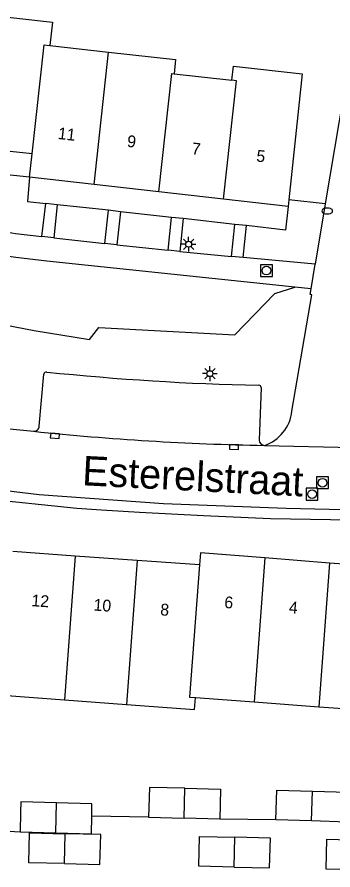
# Model space of a CAD drawing. Extents: x 132994 to 136000, y 393499 to 395512.
# Drawn here: x 133760.3 to 133787.1, y 394879.5 to 394951.9 of the extents above; entities that cross this region are included whole.
import ezdxf

# ---------------------------------------------------------------- set-up
doc = ezdxf.new("R2010")
doc.units = 0
for name, color, linetype in [('gg-afsc-erfafscheiding', 7, 'Continuous'), ('gg-afsc-hekwerk', 7, 'Continuous'), ('gg-anno-huisnummerreeks BGT', 7, 'Continuous'), ('gg-anno-openbare ruimte label', 7, 'Continuous'), ('gg-bbg-bijgebouw', 7, 'Continuous'), ('gg-bbg-hoofdgebouw', 7, 'Continuous'), ('gg-bbg-tussenscheiding', 7, 'Continuous'), ('gg-knt-verharding', 7, 'Continuous'), ('gg-knt-verharding nz', 7, 'Continuous'), ('gt-grn-groengrens', 7, 'Continuous'), ('gt-grn-vlakafsluiter', 7, 'Continuous'), ('gt-grn-weggrens', 7, 'Continuous'), ('gt-symb-brandkraan', 7, 'Continuous'), ('gt-symb-kolk', 7, 'Continuous'), ('gt-symb-lichtmast', 7, 'Continuous'), ('gt-symb-rioolschacht', 7, 'Continuous')]:
    doc.layers.add(name, color=color, linetype=linetype)

# ---------------------------------------------------------------- blocks, each defined once
blk = doc.blocks.new('gt0-BR')
at = {"layer": 'gt-symb-brandkraan'}
for centre, radius, start, end in [((-0.244, 0), 0.206, 107.56694, 252.43307), ((0.599, -2.664), 3, 106.89205, 107.56694), ((0, -0.691), 0.938, 73.10799, 106.89205), ((-0.599, -2.664), 3, 72.43309, 73.10799), ((0.244, 0), 0.206, 287.56695, 72.43309), ((0.599, 2.664), 3, 252.43307, 253.10797), ((0, 0.691), 0.938, 253.10797, 286.89206), ((-0.599, 2.664), 3, 286.89206, 287.56695)]:
    blk.add_arc(centre, radius, start, end, dxfattribs=at)
blk = doc.blocks.new('gt0-RS')
at = {"layer": 'gt-symb-rioolschacht'}
blk.add_lwpolyline([(-0.5, -0.5), (0.5, -0.5), (0.5, 0.5), (-0.5, 0.5)], close=True, dxfattribs=at)
blk.add_circle((0, 0), 0.375, dxfattribs=at)
blk = doc.blocks.new('gt0-LMAST')
at = {"layer": 'gt-symb-lichtmast'}
for p, q in [((-0.182, 0.173), (-0.447, 0.438)), ((-0.005, 0.246), (-0.005, 0.621)), ((0.172, 0.173), (0.437, 0.438)), ((-0.255, -0.004), (-0.63, -0.004)), ((-0.182, -0.181), (-0.447, -0.446)), ((-0.005, -0.254), (-0.005, -0.629)), ((0.437, -0.446), (0.172, -0.181)), ((0.245, -0.004), (0.62, -0.004))]:
    blk.add_line(p, q, dxfattribs=at)
blk.add_circle((-0.005, -0.004), 0.25, dxfattribs=at)
blk = doc.blocks.new('gt0-KOLK')
at = {"layer": 'gt-symb-kolk'}
blk.add_lwpolyline([(0, 0), (0.375, 0), (0.375, 0.4), (-0.375, 0.4), (-0.375, 0), (0, 0)], dxfattribs=at)

msp = doc.modelspace()

# ---------------------------------------------------------------- linework, layer by layer
at = {"layer": 'gg-afsc-erfafscheiding'}
for p, q in [((133771.458, 394883.991), (133766.623, 394884.084)), ((133782.257, 394883.762), (133777.502, 394883.836)), ((133757.915, 394882.911), (133760.541, 394882.748))]:
    msp.add_line(p, q, dxfattribs=at)
at = {"layer": 'gg-afsc-hekwerk'}
for p, q in [((133789.305, 394953.107), (133786.435, 394936.039)), ((133786.435, 394936.039), (133783.351, 394936.365))]:
    msp.add_line(p, q, dxfattribs=at)
at = {"layer": 'gg-bbg-bijgebouw'}
for p, q in [((133760.585, 394884.425), (133760.541, 394882.748)), ((133766.594, 394882.589), (133766.623, 394884.084)), ((133771.458, 394883.991), (133774.48, 394883.914)), ((133777.502, 394883.836), (133774.48, 394883.914)), ((133785.287, 394883.675), (133782.257, 394883.762)), ((133788.317, 394883.587), (133785.287, 394883.675)), ((133760.541, 394882.748), (133763.568, 394882.668)), ((133763.568, 394882.668), (133766.594, 394882.589))]:
    msp.add_line(p, q, dxfattribs=at)
for points in [[(133774.542, 394886.451), (133771.518, 394886.527), (133771.458, 394883.991)], [(133774.542, 394886.451), (133777.566, 394886.375), (133777.502, 394883.836)], [(133782.257, 394883.762), (133782.331, 394886.301), (133785.357, 394886.212)], [(133785.357, 394886.212), (133788.382, 394886.124), (133788.317, 394883.587)], [(133763.625, 394885.209), (133760.607, 394885.287), (133760.585, 394884.425)], [(133766.623, 394884.084), (133766.643, 394885.13), (133763.625, 394885.209)], [(133764.31, 394880.057), (133761.296, 394880.132), (133761.36, 394882.672), (133764.375, 394882.596)], [(133764.31, 394880.057), (133767.325, 394879.981), (133767.389, 394882.52), (133764.375, 394882.596)], [(133778.718, 394879.76), (133775.709, 394879.831), (133775.77, 394882.37), (133778.778, 394882.299)], [(133778.718, 394879.76), (133781.727, 394879.688), (133781.787, 394882.228), (133778.778, 394882.299)], [(133789.539, 394879.522), (133786.529, 394879.584), (133786.582, 394882.124), (133789.592, 394882.061)]]:
    msp.add_lwpolyline(points, dxfattribs=at)
at = {"layer": 'gg-bbg-hoofdgebouw'}
for p, q in [((133763.075, 394949.456), (133768.061, 394948.9)), ((133773.612, 394947.062), (133778.518, 394946.516)), ((133761.574, 394940.266), (133756.303, 394940.845)), ((133761.354, 394938.285), (133761.574, 394940.266)), ((133766.838, 394937.663), (133761.354, 394938.285)), ((133772.323, 394937.041), (133766.838, 394937.663)), ((133777.807, 394936.419), (133772.323, 394937.041)), ((133783.291, 394935.797), (133777.807, 394936.419)), ((133783.351, 394936.365), (133783.291, 394935.797)), ((133765.217, 394906.152), (133759.945, 394906.525)), ((133770.488, 394905.779), (133765.217, 394906.152)), ((133786.81, 394905.557), (133781.331, 394905.988)), ((133775.76, 394905.406), (133770.488, 394905.779)), ((133792.29, 394905.127), (133786.81, 394905.557)), ((133759.041, 394894.34), (133764.312, 394893.954)), ((133764.312, 394893.954), (133769.582, 394893.568)), ((133775.43, 394894.145), (133780.425, 394893.775)), ((133780.425, 394893.775), (133785.906, 394893.369)), ((133785.906, 394893.369), (133791.591, 394892.948))]:
    msp.add_line(p, q, dxfattribs=at)
for points in [[(133757.199, 394949.706), (133757.466, 394952.097), (133763.298, 394951.444), (133763.075, 394949.456)], [(133768.061, 394948.9), (133773.744, 394948.267), (133773.612, 394947.062)], [(133778.518, 394946.516), (133778.653, 394947.719), (133784.481, 394947.064), (133783.351, 394936.365)], [(133781.331, 394905.988), (133775.851, 394906.418), (133775.76, 394905.406)], [(133769.582, 394893.568), (133775.354, 394893.146), (133775.43, 394894.145)]]:
    msp.add_lwpolyline(points, dxfattribs=at)
at = {"layer": 'gg-bbg-tussenscheiding'}
for p, q in [((133766.838, 394937.663), (133768.061, 394948.9)), ((133765.217, 394906.152), (133764.312, 394893.954)), ((133781.331, 394905.988), (133780.425, 394893.775)), ((133770.488, 394905.779), (133769.582, 394893.568)), ((133786.81, 394905.557), (133785.906, 394893.369)), ((133774.48, 394883.914), (133774.542, 394886.451)), ((133785.287, 394883.675), (133785.357, 394886.212)), ((133763.568, 394882.668), (133763.625, 394885.209)), ((133764.31, 394880.057), (133764.375, 394882.596)), ((133778.718, 394879.76), (133778.778, 394882.299))]:
    msp.add_line(p, q, dxfattribs=at)
for points in [[(133761.574, 394940.266), (133762.58, 394949.511), (133763.075, 394949.456)], [(133772.323, 394937.041), (133773.416, 394947.084), (133773.612, 394947.062)], [(133777.807, 394936.419), (133778.901, 394946.473), (133778.518, 394946.516)], [(133775.76, 394905.406), (133774.927, 394894.182), (133775.43, 394894.145)]]:
    msp.add_lwpolyline(points, dxfattribs=at)
at = {"layer": 'gg-knt-verharding'}
for p, q in [((133761.354, 394938.285), (133758.478, 394938.601)), ((133762.386, 394933.255), (133762.72, 394936.06)), ((133763.684, 394935.952), (133762.72, 394936.06)), ((133763.684, 394935.952), (133763.412, 394933.141)), ((133768.059, 394935.483), (133763.684, 394935.952)), ((133786.435, 394936.039), (133785.588, 394930.905)), ((133767.737, 394932.671), (133768.059, 394935.483)), ((133769.074, 394935.368), (133768.059, 394935.483)), ((133769.074, 394935.368), (133768.754, 394932.558)), ((133773.4, 394934.872), (133769.074, 394935.368)), ((133773.103, 394932.101), (133773.4, 394934.872)), ((133774.386, 394934.775), (133773.4, 394934.872)), ((133774.386, 394934.775), (133774.101, 394931.987)), ((133778.77, 394934.278), (133774.386, 394934.775)), ((133778.484, 394931.564), (133778.77, 394934.278)), ((133779.771, 394934.183), (133778.77, 394934.278)), ((133779.468, 394931.478), (133779.771, 394934.183)), ((133763.412, 394933.141), (133762.386, 394933.255)), ((133763.412, 394933.141), (133767.737, 394932.671)), ((133768.754, 394932.558), (133767.737, 394932.671)), ((133768.754, 394932.558), (133773.103, 394932.101)), ((133774.101, 394931.987), (133773.103, 394932.101)), ((133774.101, 394931.987), (133778.484, 394931.564)), ((133779.468, 394931.478), (133778.484, 394931.564)), ((133785.588, 394930.905), (133779.468, 394931.478)), ((133785.244, 394928.81), (133783.857, 394928.956)), ((133762.165, 394917.161), (133762.564, 394921.589)), ((133781.01, 394920.452), (133780.839, 394915.995)), ((133759.68, 394916.958), (133761.698, 394916.736))]:
    msp.add_line(p, q, dxfattribs=at)
for points in [[(133761.354, 394938.285), (133761.172, 394936.226), (133762.72, 394936.06)], [(133783.291, 394935.797), (133783.066, 394933.809), (133779.771, 394934.183)], [(133783.857, 394928.956), (133762.808, 394931.174), (133760.198, 394931.468), (133758.542, 394931.717), (133757.019, 394932.05), (133754.664, 394932.662), (133751.569, 394933.436), (133750.125, 394933.754), (133748.508, 394934.067), (133747.291, 394934.262), (133745.966, 394934.42), (133744.197, 394934.56), (133742.868, 394934.609), (133741.429, 394934.614), (133740.938, 394934.587), (133740.577, 394934.514), (133740.21, 394934.368), (133739.836, 394934.124), (133739.598, 394933.881), (133739.383, 394933.586), (133739.167, 394933.097), (133739.023, 394932.554), (133738.938, 394932.002)], [(133757.962, 394933.908), (133760.149, 394933.506), (133762.386, 394933.255)], [(133783.621, 394918.441), (133785.302, 394928.306), (133785.177, 394928.33), (133785.244, 394928.81)], [(133792.763, 394909.128), (133786.892, 394909.236), (133781.809, 394909.31), (133776.125, 394909.577), (133770.682, 394909.854), (133767.444, 394910.035), (133765.369, 394910.183), (133757.147, 394911.025), (133755.09, 394911.267), (133751.549, 394911.747), (133749.282, 394912.083), (133744.071, 394912.918), (133740.605, 394913.512), (133738.386, 394913.916), (133735.537, 394914.513)]]:
    msp.add_lwpolyline(points, dxfattribs=at)
for centre, radius, start, end in [((133762.786, 394921.534), 0.229, 83.57278, 166.22498), ((133785.583, 395141.926), 221.338, 264.09508, 268.76493), ((133780.814, 394920.442), 0.197, 2.81032, 90.46283), ((133780.184, 394918.819), 3.457, 288.47469, 353.72081), ((133761.727, 394917.173), 0.438, 266.17455, 358.43386), ((133781.302, 394916.003), 0.463, 180.97499, 267.23466)]:
    msp.add_arc(centre, radius, start, end, dxfattribs=at)
at = {"layer": 'gg-knt-verharding nz'}
msp.add_lwpolyline([(133792.868, 394909.961), (133783.13, 394910.185), (133772.724, 394910.589), (133762.174, 394911.35), (133751.788, 394912.599), (133741.558, 394914.222), (133731.785, 394916.222), (133721.575, 394918.692), (133711.788, 394921.295), (133711.584, 394920.427)], dxfattribs=at)
msp.add_arc((133785.283, 395141.992), 226.488, 264.02264, 268.98719, dxfattribs=at)
at = {"layer": 'gt-grn-groengrens'}
msp.add_lwpolyline([(133738.938, 394932.002), (133743.198, 394931.834), (133744.153, 394930.422), (133749.564, 394928.043), (133755.721, 394926.457), (133761.746, 394925.296), (133766.435, 394924.533), (133767.243, 394925.549), (133778.769, 394924.923), (133782.168, 394928.436), (133783.857, 394928.956)], dxfattribs=at)
at = {"layer": 'gt-grn-vlakafsluiter'}
msp.add_line((133785.244, 394928.81), (133785.588, 394930.905), dxfattribs=at)
at = {"layer": 'gt-grn-weggrens'}
msp.add_line((133781.28, 394915.54), (133792.765, 394915.259), dxfattribs=at)

# ---------------------------------------------------------------- block references
at = {"layer": 'gt-symb-brandkraan'}
msp.add_blockref('gt0-BR', (133786.611, 394935.426), dxfattribs=at)
at = {"layer": 'gt-symb-kolk'}
for p, rotation in [((133763.522, 394916.552), 174.40664495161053), ((133778.708, 394915.6), 178.18387364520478)]:
    msp.add_blockref('gt0-KOLK', p, dxfattribs=dict(at, rotation=rotation))
at = {"layer": 'gt-symb-lichtmast'}
for p in [(133774.856, 394932.606), (133776.664, 394921.63)]:
    msp.add_blockref('gt0-LMAST', p, dxfattribs=at)
at = {"layer": 'gt-symb-rioolschacht'}
for p in [(133781.456, 394930.371), (133786.214, 394912.369), (133785.33, 394911.404)]:
    msp.add_blockref('gt0-RS', p, dxfattribs=at)

# ---------------------------------------------------------------- texts
at = {"layer": 'gg-anno-huisnummerreeks BGT'}
for s, rotation, p in [('11', 353.5, (133763.719, 394941.54)), ('9', 353.5, (133769.589, 394940.874)), ('7', 353.5, (133775.074, 394940.252)), ('5', 353.5, (133780.558, 394939.63)), ('12', 356, (133761.489, 394901.903)), ('10', 356, (133766.76, 394901.53)), ('6', 355.5, (133777.852, 394901.747)), ('4', 355.5, (133783.331, 394901.317)), ('8', 356, (133772.419, 394901.13))]:
    msp.add_text(s, height=1, rotation=rotation, dxfattribs=at).set_placement(p)
at = {"layer": 'gg-anno-openbare ruimte label'}
msp.add_text('Esterelstraat', height=2.5, rotation=357.1, dxfattribs=at).set_placement((133765.777, 394912.161))

doc.saveas('drawing.dxf')
